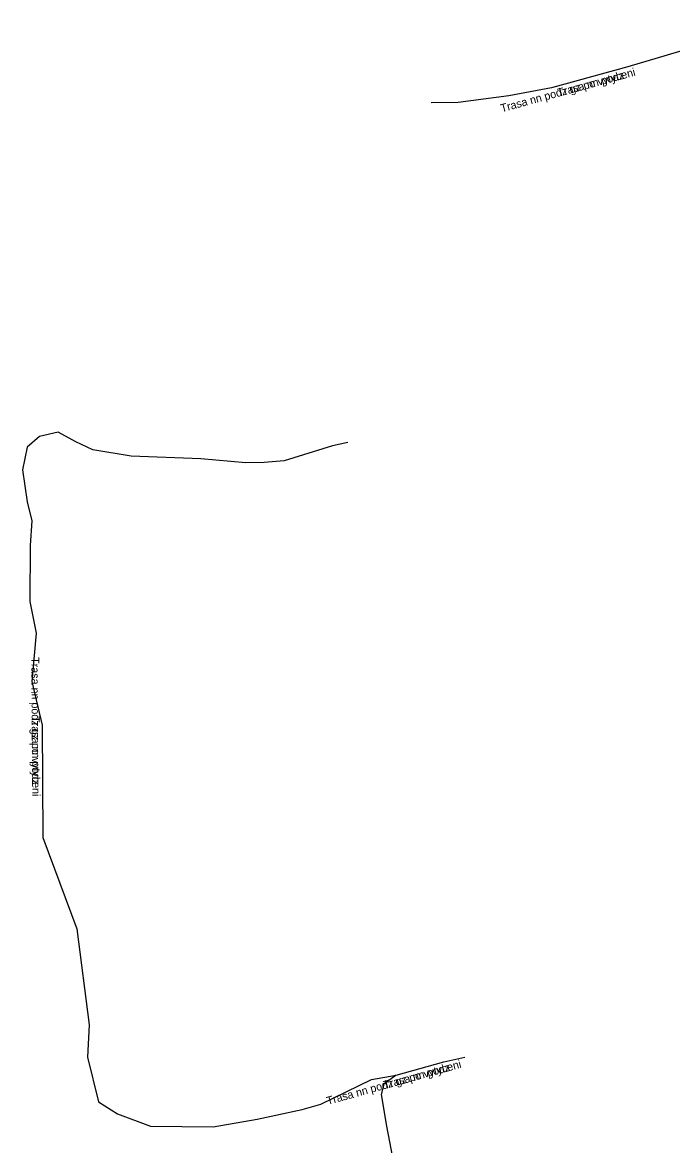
# Model space of a CAD drawing. Extents: x -876384 to -875659, y -1020218 to -1019588.
# Drawn here: x -876069.7 to -876029.1, y -1019934.7 to -1019864.6 of the extents above; entities that cross this region are included whole.
import ezdxf

# ---------------------------------------------------------------- set-up
doc = ezdxf.new("R2010")
doc.units = 0
doc.layers.add('Popiskový text - Ostatní atributy Trasy', color=7, linetype='Continuous')
doc.layers.add('Spojnice NN', color=7, linetype='Continuous')

msp = doc.modelspace()

# ---------------------------------------------------------------- linework, layer by layer
at = {"layer": 'Spojnice NN'}
for points in [[(-876022.75, -1019864.59), (-876024.97, -1019865.23), (-876026.93, -1019865.91), (-876031.84, -1019867.37), (-876036.61, -1019868.68), (-876039.29, -1019869.18), (-876042.44, -1019869.59), (-876044.13, -1019869.61)], [(-876022.75, -1019864.59), (-876024.97, -1019865.23), (-876026.93, -1019865.91), (-876031.84, -1019867.37), (-876036.61, -1019868.68), (-876039.29, -1019869.18), (-876042.44, -1019869.59), (-876044.13, -1019869.61)], [(-876049.34, -1019890.83), (-876050.3, -1019891.04), (-876053.31, -1019891.98), (-876054.56, -1019892.08), (-876055.71, -1019892.11), (-876058.52, -1019891.87), (-876062.86, -1019891.7), (-876065.26, -1019891.3), (-876066.32, -1019890.8), (-876067.42, -1019890.2), (-876068.59, -1019890.47), (-876069.36, -1019891.14), (-876069.66, -1019892.54), (-876069.37, -1019894.55), (-876069.07, -1019895.73), (-876069.17, -1019897.27), (-876069.19, -1019900.77), (-876068.8, -1019902.76), (-876069.08, -1019905.78), (-876068.43, -1019908.5), (-876068.38, -1019915.52), (-876066.27, -1019921.23), (-876065.49, -1019927.23), (-876065.6, -1019929.25), (-876064.92, -1019932.03), (-876063.72, -1019932.79), (-876061.66, -1019933.57), (-876057.75, -1019933.6), (-876055, -1019933.12), (-876052.18, -1019932.52), (-876051.03, -1019932.19), (-876047.85, -1019930.64), (-876046.32, -1019930.37)], [(-876049.34, -1019890.83), (-876050.3, -1019891.04), (-876053.31, -1019891.98), (-876054.56, -1019892.08), (-876055.71, -1019892.11), (-876058.52, -1019891.87), (-876062.86, -1019891.7), (-876065.26, -1019891.3), (-876066.32, -1019890.8), (-876067.42, -1019890.2), (-876068.59, -1019890.47), (-876069.36, -1019891.14), (-876069.66, -1019892.54), (-876069.37, -1019894.55), (-876069.07, -1019895.73), (-876069.17, -1019897.27), (-876069.19, -1019900.77), (-876068.8, -1019902.76), (-876069.08, -1019905.78), (-876068.43, -1019908.5), (-876068.38, -1019915.52), (-876066.27, -1019921.23), (-876065.49, -1019927.23), (-876065.6, -1019929.25), (-876064.92, -1019932.03), (-876063.72, -1019932.79), (-876061.66, -1019933.57), (-876057.75, -1019933.6), (-876055, -1019933.12), (-876052.18, -1019932.52), (-876051.03, -1019932.19), (-876047.85, -1019930.64), (-876046.32, -1019930.37)], [(-876046.32, -1019930.37), (-876043.85, -1019929.68), (-876043.34, -1019929.54), (-876042.02, -1019929.24)], [(-876046.32, -1019930.37), (-876043.85, -1019929.68), (-876043.34, -1019929.54), (-876042.02, -1019929.24)], [(-876046.32, -1019930.37), (-876047.08, -1019930.93), (-876047.26, -1019931.59), (-876046.92, -1019933.56), (-876045.88, -1019938.99), (-876044.61, -1019943.83), (-876044.42, -1019946.2), (-876043.76, -1019948.18), (-876043.34, -1019949.51), (-876043.03, -1019949.85), (-876042.41, -1019950.34), (-876039.62, -1019949.85), (-876034.17, -1019949.16), (-876030.99, -1019948.63), (-876028.02, -1019948.16), (-876024.37, -1019947.45), (-876019.01, -1019946.41), (-876015.26, -1019945.54), (-876012.33, -1019944.94), (-876009.41, -1019944.24), (-876005.45, -1019943.4), (-876003.75, -1019943.35), (-875999.53, -1019943.84)], [(-876046.32, -1019930.37), (-876047.08, -1019930.93), (-876047.26, -1019931.59), (-876046.92, -1019933.56), (-876045.88, -1019938.99), (-876044.61, -1019943.83), (-876044.42, -1019946.2), (-876043.76, -1019948.18), (-876043.34, -1019949.51), (-876043.03, -1019949.85), (-876042.41, -1019950.34), (-876039.62, -1019949.85), (-876034.17, -1019949.16), (-876030.99, -1019948.63), (-876028.02, -1019948.16), (-876024.37, -1019947.45), (-876019.01, -1019946.41), (-876015.26, -1019945.54), (-876012.33, -1019944.94), (-876009.41, -1019944.24), (-876005.45, -1019943.4), (-876003.75, -1019943.35), (-875999.53, -1019943.84)]]:
    msp.add_lwpolyline(points, dxfattribs=at)

# ---------------------------------------------------------------- texts
at = {"layer": 'Popiskový text - Ostatní atributy Trasy'}
for s, rotation, p in [('Trasa nn podz gz po vytyceni', 15.35671, (-876039.719, -1019870.208)), ('Trasa nn podz', 15.35671, (-876036.165, -1019869.232)), ('Trasa nn podz gz po vytyceni', 270.40808, (-876069.111, -1019904.259)), ('Trasa nn podz', 270.40808, (-876069.084, -1019907.944)), ('Trasa nn podz gz po vytyceni', 15.60782, (-876050.584, -1019932.236)), ('Trasa nn podz', 15.60782, (-876047.035, -1019931.245))]:
    msp.add_text(s, height=0.5, rotation=rotation, dxfattribs=at).set_placement(p)

doc.saveas('drawing.dxf')
